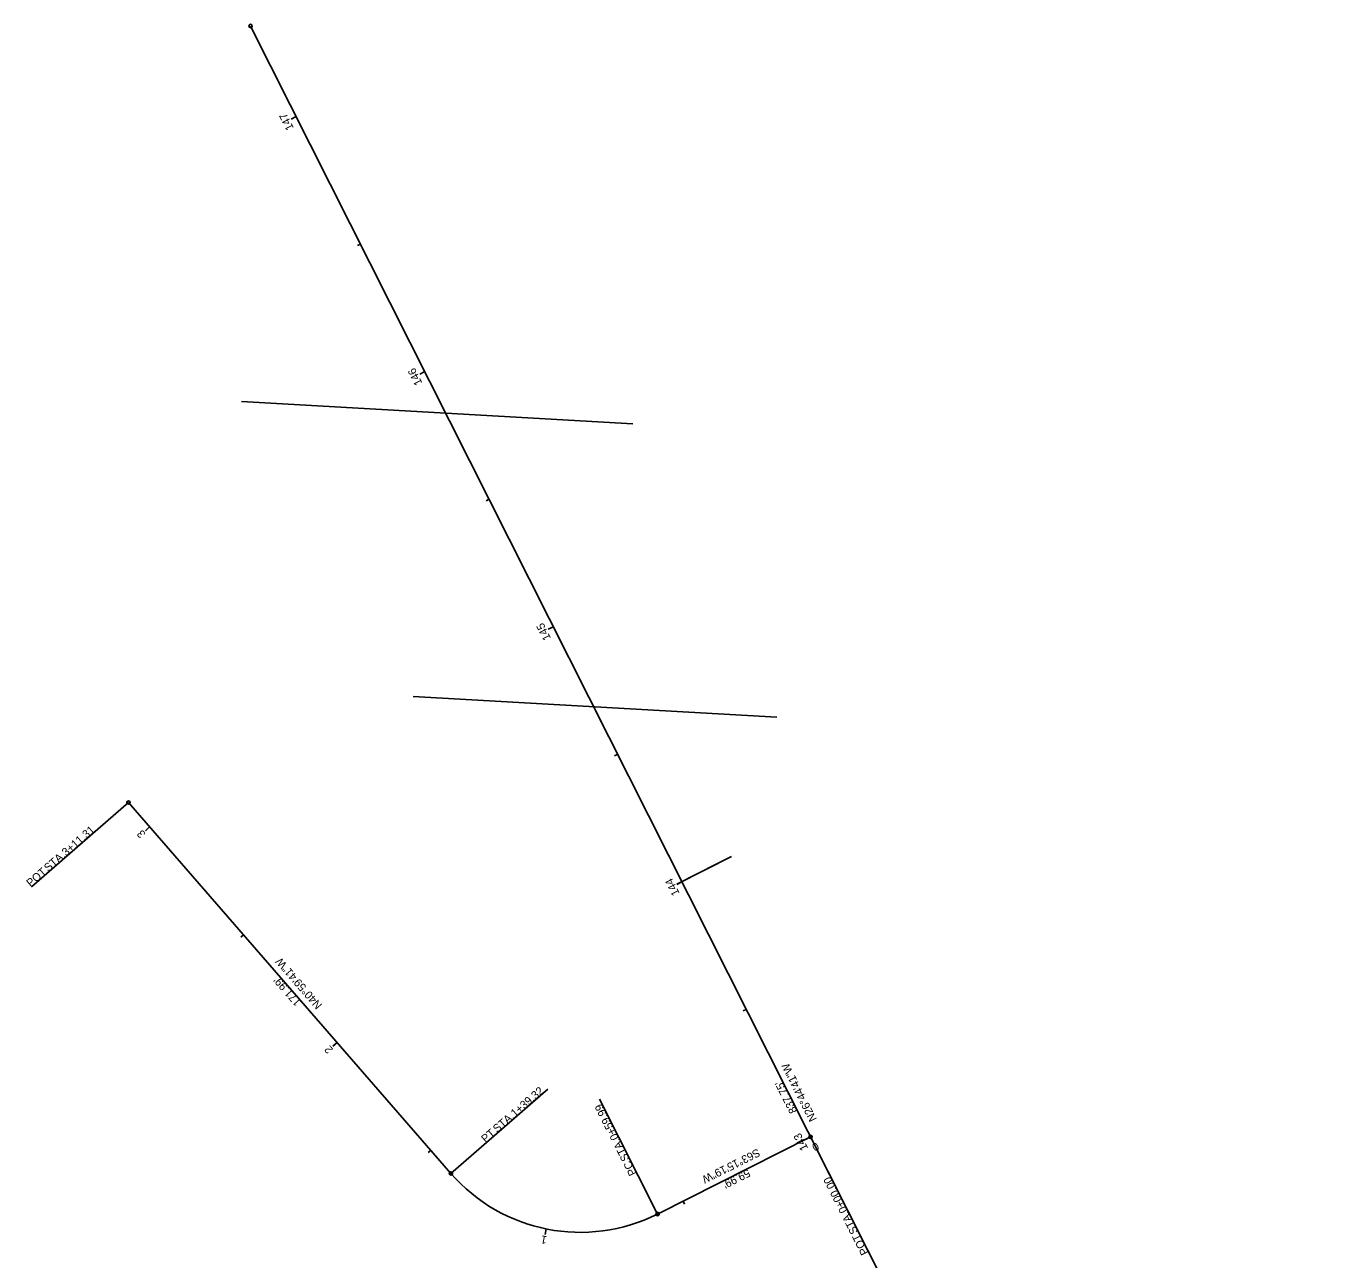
# Model space of a CAD drawing. Extents: x 1359387 to 1360093, y 668188 to 669559.
# Drawn here: x 1359636.9 to 1360092.5, y 668525.3 to 668957.3 of the extents above; entities that cross this region are included whole.
import ezdxf

# ---------------------------------------------------------------- set-up
doc = ezdxf.new("R2010")
doc.units = 0
for name, color, linetype in [('_CIVIL_CONSTRUCTION', 7, 'Continuous'), ('Default', 7, 'Continuous'), ('MD_P_Surface_Finished_Grade', 7, 'Continuous'), ('SC_Scratch4', 7, 'Continuous'), ('SH_Border', 7, 'Continuous'), ('SH_Data', 7, 'Continuous'), ('SH_Named_Boundary', 7, 'Continuous'), ('SH_Text', 7, 'Continuous')]:
    doc.layers.add(name, color=color, linetype=linetype)

msp = doc.modelspace()

# ---------------------------------------------------------------- linework, layer by layer
at = {"layer": 'Default'}
for p, q in [((1360092.49, 668209.18), (1359715.49, 668957.31)), ((1359785.59, 668555.65), (1359672.77, 668685.47)), ((1359911.46, 668568.43), (1359906.28, 668578.7)), ((1359911.46, 668568.43), (1359857.88, 668541.43)), ((1359915.4, 668560.6), (1359922.08, 668547.35))]:
    msp.add_line(p, q, dxfattribs=at)
msp.add_arc((1359830.88, 668595.01), 60, 220.9947, 296.7447, dxfattribs=at)
at = {"layer": 'MD_P_Surface_Finished_Grade'}
for p in [(1359883.79, 668666.54), (1359878.93, 668664.1)]:
    msp.add_line(p, (1359864.64, 668656.9), dxfattribs=at)
at = {"layer": 'SC_Scratch4'}
for p, q in [((1359712.37, 668825.86), (1359849.27, 668818.08)), ((1359772.35, 668722.59), (1359899.61, 668715.36)), ((1359835.52, 668719.02), (1359835.58, 668719.02)), ((1359835.58, 668719.02), (1359835.58, 668719.02))]:
    msp.add_line(p, q, dxfattribs=at)
at = {"layer": 'SH_Data'}
for p, q in [((1359672.77, 668685.47), (1359638.8, 668655.95)), ((1359785.59, 668555.65), (1359819.56, 668585.17)), ((1359857.88, 668541.43), (1359837.63, 668581.61)), ((1359911.46, 668568.43), (1359931.71, 668528.24))]:
    msp.add_line(p, q, dxfattribs=at)
for centre in [(1359715.49, 668957.31), (1359672.77, 668685.47), (1359911.46, 668568.43), (1359785.59, 668555.65), (1359857.88, 668541.43)]:
    msp.add_circle(centre, 0.6, dxfattribs=at)
at = {"layer": 'SH_Named_Boundary'}
for p, q in [((1360092.49, 668209.18), (1359715.49, 668957.31)), ((1359785.59, 668555.65), (1359672.77, 668685.47)), ((1359911.46, 668568.43), (1359857.88, 668541.43))]:
    msp.add_line(p, q, dxfattribs=at)
msp.add_arc((1359830.88, 668595.01), 60, 220.9947, 296.7447, dxfattribs=at)
at = {"layer": 'SH_Text'}
for p, q in [((1359731.45, 668925.64), (1359729.67, 668924.74)), ((1359753.95, 668880.98), (1359752.88, 668880.44)), ((1359776.45, 668836.33), (1359774.67, 668835.43)), ((1359798.95, 668791.68), (1359797.88, 668791.14)), ((1359821.45, 668747.03), (1359819.67, 668746.13)), ((1359843.95, 668702.38), (1359842.88, 668701.84)), ((1359680.19, 668676.93), (1359678.68, 668675.62)), ((1359866.46, 668657.73), (1359864.67, 668656.83)), ((1359712.99, 668639.19), (1359712.08, 668638.4)), ((1359888.96, 668613.08), (1359887.88, 668612.54)), ((1359745.79, 668601.45), (1359744.28, 668600.14)), ((1359911.46, 668568.43), (1359909.67, 668567.53)), ((1359911.46, 668568.43), (1359912.36, 668566.64)), ((1359778.59, 668563.71), (1359777.68, 668562.93)), ((1359866.81, 668545.93), (1359867.35, 668544.85)), ((1359818.96, 668536.21), (1359818.56, 668534.25))]:
    msp.add_line(p, q, dxfattribs=at)

# ---------------------------------------------------------------- texts
at = {"layer": '_CIVIL_CONSTRUCTION'}
for s, rotation, p in [("171.99'", 130.9947, (1359733.38, 668615.68)), ("837.75'", 116.7446, (1359906.85, 668577.48)), ("59.99'", 206.7447, (1359889.44, 668557.29))]:
    msp.add_text(s, height=2.8, rotation=rotation, dxfattribs=at).set_placement(p)
at = {"layer": 'SH_Border'}
for s, rotation, p in [('N40°59\'41"W', 130.9947, (1359740.7, 668614.63)), ('N26°44\'41"W', 116.7446, (1359913.69, 668574.66)), ('S63°15\'19"W', 206.7447, (1359892.89, 668564.44))]:
    msp.add_text(s, height=2.8, rotation=rotation, dxfattribs=at).set_placement(p)
at = {"layer": 'SH_Data'}
for s, rotation, p in [('3+11.31', 40.9947, (1359650.95, 668666.56)), (' STA. ', 40.9947, (1359643.92, 668660.44)), ('POT', 40.9947, (1359638.54, 668655.76)), ('1+39.32', 40.9947, (1359808.03, 668575.2)), (' STA. ', 40.9947, (1359800.99, 668569.08)), ('0+59.99', 116.7447, (1359844.41, 668568.08)), ('PT', 40.9947, (1359797.71, 668566.23)), (' STA. ', 116.7447, (1359848.61, 668559.76)), ('PC', 116.7447, (1359850.68, 668555.65)), ('0+00.00', 116.7447, (1359924.44, 668542.59)), (' STA. ', 116.7447, (1359928.63, 668534.26)), ('POT', 116.7447, (1359931.84, 668527.9))]:
    msp.add_text(s, height=2.8, rotation=rotation, dxfattribs=at).set_placement(p)
at = {"layer": 'SH_Text'}
for s, rotation, p in [('147', 116.7446, (1359730.68, 668921.61)), ('146', 116.7446, (1359775.68, 668832.3)), ('145', 116.7446, (1359820.66, 668743.04)), ('3', 130.9947, (1359678.93, 668674.56)), ('144', 116.7446, (1359865.7, 668653.67)), ('2', 130.9947, (1359744.54, 668599.07)), ('143', 116.7446, (1359910.66, 668564.45)), ('0', 206.7447, (1359913.5, 668566.66)), ('1', 168.5411, (1359819.43, 668533.56))]:
    msp.add_text(s, height=2.8, rotation=rotation, dxfattribs=at).set_placement(p)

doc.saveas('drawing.dxf')
